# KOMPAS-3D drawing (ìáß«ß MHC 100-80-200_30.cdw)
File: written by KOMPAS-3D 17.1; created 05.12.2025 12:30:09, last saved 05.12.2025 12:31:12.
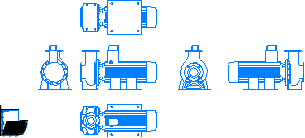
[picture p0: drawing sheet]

Sheet 1: A4, portrait

Title block, sheet 1: name: Насос MHC 100-80-200_30 / 30,0 кВт 3х380В; material: Сталь 10  ГОСТ 1050-88; mass: 310,89; sheets: 1; sheet format: A4

Views: Проекционный вид 2, Проекционный вид 3, Проекционный вид 4, Проекционный вид 5, Проекционный вид 6
Referenced files in \\adlc.lan\data\АДЛ_ПКД\3D-модели\ADL production\Насосы ГРАНПАМП\Насосы ГРАНПАМП серии МНС\KOMPAS 3D\: Насос MHC 100-80-200_30.m3d
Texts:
  Andrey
  АДЛ
Dimensions and other numbers on the sheet: 1:1; 1; 30,0 кВт 3х380В; 310,89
